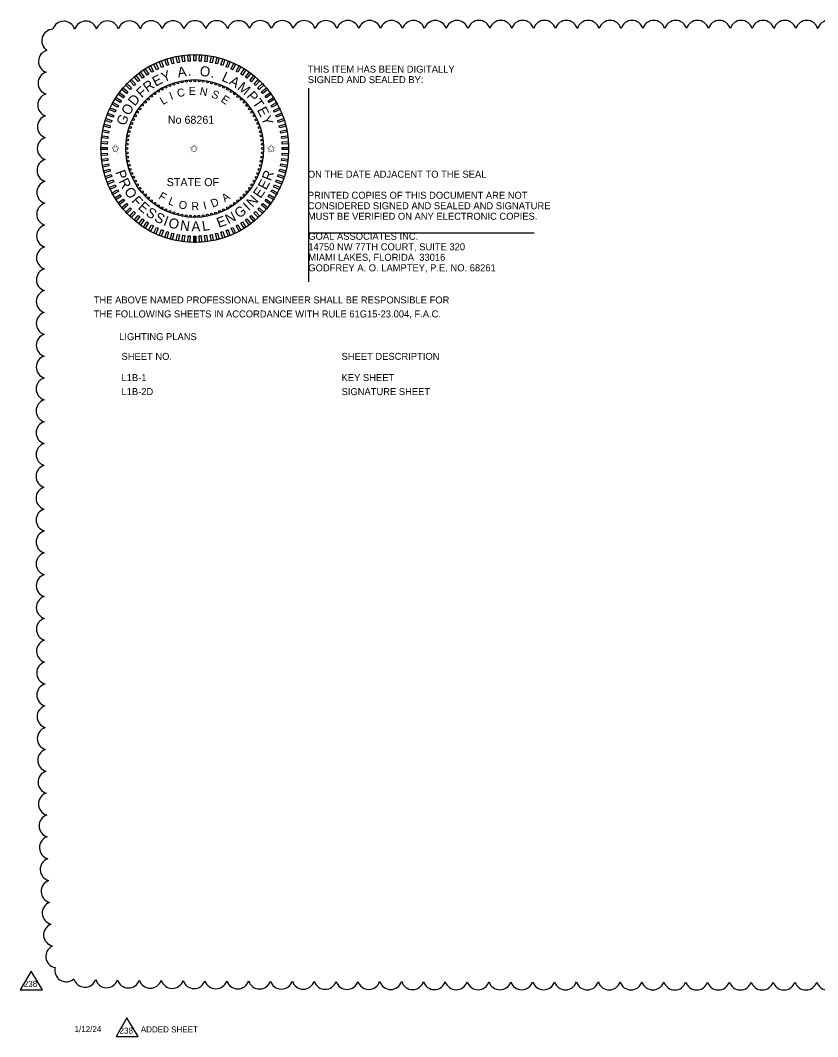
# Model space of a CAD drawing. Extents: x -811.2 to -767.6, y -2295.2 to -2235.1.
# Drawn here: x -811.23 to -803.27, y -2294.97 to -2284.82 of the extents above; entities that cross this region are included whole.
import ezdxf

# ---------------------------------------------------------------- set-up
doc = ezdxf.new("R2010")
doc.units = 0
for name, color, linetype in [('AdhocPoint_dp', 7, 'Continuous'), ('Cloud_dp', 7, 'Continuous'), ('PlotBorder_dp', 7, 'Continuous'), ('TextMinor', 7, 'Continuous'), ('TextMisc', 7, 'Continuous'), ('TextShtNo', 7, 'Continuous')]:
    doc.layers.add(name, color=color, linetype=linetype)

msp = doc.modelspace()

# ---------------------------------------------------------------- linework, layer by layer
at = {"layer": 'AdhocPoint_dp'}
for p, q in [((-808.355, -2285.496), (-808.355, -2287.431)), ((-808.355, -2286.941), (-806.098, -2286.941))]:
    msp.add_line(p, q, dxfattribs=at)
at = {"layer": 'Cloud_dp'}
for points in [[(-811.125, -2294.318), (-811.233, -2294.506), (-811.012, -2294.506)], [(-810.168, -2294.785), (-810.276, -2294.973), (-810.055, -2294.973)]]:
    msp.add_lwpolyline(points, close=True, dxfattribs=at)
for centre, start, end in [((-810.798, -2284.941), 18.0566, 163.0566), ((-810.58, -2284.94), 17.7998, 162.7998), ((-810.362, -2284.939), 17.7187, 162.7187), ((-810.143, -2284.938), 17.6743, 162.6743), ((-809.925, -2284.937), 17.6451, 162.6451), ((-809.707, -2284.937), 17.624, 162.624), ((-809.488, -2284.936), 17.6079, 162.6079), ((-809.27, -2284.936), 17.5951, 162.5951), ((-809.052, -2284.936), 17.5845, 162.5845), ((-808.834, -2284.935), 17.5756, 162.5756), ((-808.615, -2284.935), 17.568, 162.568), ((-808.397, -2284.935), 17.5614, 162.5614), ((-808.179, -2284.935), 17.5556, 162.5556), ((-807.96, -2284.934), 17.5505, 162.5505), ((-807.742, -2284.934), 17.5459, 162.5459), ((-807.524, -2284.934), 17.5417, 162.5417), ((-807.305, -2284.934), 17.5379, 162.5379), ((-807.087, -2284.934), 17.5344, 162.5344), ((-806.869, -2284.934), 17.5313, 162.5313), ((-806.65, -2284.933), 17.5283, 162.5283), ((-806.432, -2284.933), 17.5256, 162.5256), ((-806.214, -2284.933), 17.5231, 162.5231), ((-805.995, -2284.933), 17.5207, 162.5207), ((-805.777, -2284.933), 17.5185, 162.5185), ((-805.559, -2284.933), 17.5164, 162.5164), ((-805.34, -2284.933), 17.5145, 162.5145), ((-805.122, -2284.933), 17.5126, 162.5126), ((-804.904, -2284.933), 17.5109, 162.5109), ((-804.685, -2284.933), 17.5092, 162.5092), ((-804.467, -2284.933), 17.5077, 162.5077), ((-804.249, -2284.933), 17.5062, 162.5062), ((-804.03, -2284.933), 17.5048, 162.5048), ((-803.812, -2284.933), 17.5034, 162.5034), ((-803.594, -2284.933), 17.5021, 162.5021), ((-803.375, -2284.933), 17.5009, 162.5009), ((-803.157, -2284.933), 17.5, 162.5), ((-810.905, -2285.022), 91.4771, 236.4771), ((-810.937, -2285.228), 105.908, 250.908), ((-810.942, -2285.446), 106.4168, 251.4168), ((-810.945, -2285.664), 106.6762, 251.6762), ((-810.948, -2285.882), 106.841, 251.841), ((-810.95, -2286.1), 106.9576, 251.9576), ((-810.952, -2286.318), 107.0457, 252.0457), ((-810.954, -2286.537), 107.1154, 252.1154), ((-810.955, -2286.755), 107.1722, 252.1722), ((-810.956, -2286.973), 107.2198, 252.2198), ((-810.957, -2287.192), 107.2603, 252.2603), ((-810.958, -2287.41), 107.2954, 252.2954), ((-810.959, -2287.628), 107.3262, 252.3262), ((-810.96, -2287.847), 107.3535, 252.3535), ((-810.96, -2288.065), 107.3779, 252.3779), ((-810.96, -2288.283), 107.3998, 252.3998), ((-810.961, -2288.501), 107.4198, 252.4198), ((-810.961, -2288.72), 107.438, 252.438), ((-810.961, -2288.938), 107.4547, 252.4547), ((-810.961, -2289.156), 107.4701, 252.4701), ((-810.962, -2289.375), 107.4843, 252.4843), ((-810.962, -2289.593), 107.499, 252.499), ((-810.961, -2289.811), 107.5356, 252.5356), ((-810.961, -2290.03), 107.5822, 252.5822), ((-810.961, -2290.248), 107.6325, 252.6325), ((-810.96, -2290.466), 107.6869, 252.6869), ((-810.959, -2290.685), 107.7461, 252.7461), ((-810.958, -2290.903), 107.8108, 252.8108), ((-810.957, -2291.121), 107.8818, 252.8818), ((-810.955, -2291.339), 107.9604, 252.9604), ((-810.954, -2291.558), 108.0479, 253.0479), ((-810.951, -2291.776), 108.1461, 253.1461), ((-810.949, -2291.994), 108.2576, 253.2576), ((-810.945, -2292.212), 108.3854, 253.3854), ((-810.942, -2292.431), 108.534, 253.534), ((-810.938, -2292.649), 108.7099, 253.7099), ((-810.932, -2292.867), 108.9225, 253.9225), ((-810.927, -2293.085), 109.1867, 254.1867), ((-810.92, -2293.303), 109.5275, 254.5275), ((-810.911, -2293.521), 109.9909, 254.9909), ((-810.9, -2293.738), 110.6749, 255.6749), ((-810.886, -2293.956), 111.8417, 256.8417), ((-810.864, -2294.171), 114.6718, 259.6718), ((-810.774, -2294.311), 166.2299, 311.2299), ((-810.588, -2294.365), 196.1072, 341.1072), ((-810.37, -2294.37), 196.5738, 341.5738), ((-810.152, -2294.373), 196.7877, 341.7877), ((-809.934, -2294.375), 196.9179, 341.9179), ((-809.715, -2294.377), 197.008, 342.008), ((-809.497, -2294.379), 197.075, 342.075), ((-809.279, -2294.381), 197.1274, 342.1274), ((-809.061, -2294.382), 197.1699, 342.1699), ((-808.842, -2294.383), 197.2052, 342.2052), ((-808.624, -2294.384), 197.2352, 342.2352), ((-808.406, -2294.385), 197.261, 342.261), ((-808.187, -2294.386), 197.2836, 342.2836), ((-807.969, -2294.387), 197.3036, 342.3036), ((-807.751, -2294.387), 197.3214, 342.3214), ((-807.532, -2294.388), 197.3374, 342.3374), ((-807.314, -2294.389), 197.3519, 342.3519), ((-807.096, -2294.389), 197.3651, 342.3651), ((-806.878, -2294.39), 197.3773, 342.3773), ((-806.659, -2294.39), 197.3884, 342.3884), ((-806.441, -2294.391), 197.3987, 342.3987), ((-806.223, -2294.391), 197.4083, 342.4083), ((-806.004, -2294.391), 197.4172, 342.4172), ((-805.786, -2294.392), 197.4256, 342.4256), ((-805.568, -2294.392), 197.4334, 342.4334), ((-805.349, -2294.392), 197.4407, 342.4407), ((-805.131, -2294.392), 197.4476, 342.4476), ((-804.913, -2294.392), 197.4542, 342.4542), ((-804.694, -2294.393), 197.4604, 342.4604), ((-804.476, -2294.393), 197.4662, 342.4662), ((-804.258, -2294.393), 197.4718, 342.4718), ((-804.039, -2294.393), 197.4771, 342.4771), ((-803.821, -2294.393), 197.4821, 342.4821), ((-803.603, -2294.393), 197.487, 342.487), ((-803.384, -2294.393), 197.4916, 342.4916), ((-803.166, -2294.393), 197.496, 342.496)]:
    msp.add_arc(centre, 0.114, start, end, dxfattribs=at)
at = {"layer": 'TextMinor'}
for radius in [0.938, 0.688]:
    msp.add_circle((-809.49, -2286.099), radius, dxfattribs=at)
at = {"layer": 'TextShtNo'}
for p, q in [((-809.5, -2287.037), (-809.5, -2286.974)), ((-809.49, -2287.037), (-809.49, -2286.974)), ((-809.48, -2287.037), (-809.48, -2286.974))]:
    msp.add_line(p, q, dxfattribs=at)
for points in [[(-809.698, -2285.249), (-809.717, -2285.254), (-809.733, -2285.194), (-809.713, -2285.189)], [(-809.644, -2285.238), (-809.664, -2285.242), (-809.676, -2285.18), (-809.656, -2285.176)], [(-809.59, -2285.23), (-809.61, -2285.232), (-809.618, -2285.17), (-809.598, -2285.168)], [(-809.535, -2285.225), (-809.555, -2285.227), (-809.559, -2285.164), (-809.539, -2285.163)], [(-809.48, -2285.224), (-809.5, -2285.224), (-809.5, -2285.162), (-809.48, -2285.162)], [(-809.425, -2285.227), (-809.445, -2285.225), (-809.441, -2285.163), (-809.421, -2285.164)], [(-809.37, -2285.232), (-809.39, -2285.23), (-809.383, -2285.168), (-809.363, -2285.17)], [(-809.316, -2285.242), (-809.336, -2285.238), (-809.324, -2285.177), (-809.304, -2285.18)], [(-809.263, -2285.254), (-809.282, -2285.249), (-809.267, -2285.189), (-809.247, -2285.194)], [(-809.95, -2285.355), (-809.967, -2285.366), (-810.001, -2285.313), (-809.984, -2285.302)], [(-809.903, -2285.328), (-809.92, -2285.337), (-809.951, -2285.283), (-809.933, -2285.273)], [(-809.853, -2285.303), (-809.872, -2285.312), (-809.898, -2285.255), (-809.88, -2285.247)], [(-809.803, -2285.282), (-809.822, -2285.289), (-809.845, -2285.231), (-809.826, -2285.224)], [(-809.751, -2285.264), (-809.77, -2285.27), (-809.789, -2285.211), (-809.77, -2285.205)], [(-809.21, -2285.27), (-809.229, -2285.264), (-809.21, -2285.205), (-809.191, -2285.211)], [(-809.159, -2285.289), (-809.177, -2285.282), (-809.154, -2285.224), (-809.136, -2285.231)], [(-809.108, -2285.312), (-809.127, -2285.303), (-809.1, -2285.247), (-809.082, -2285.255)], [(-809.06, -2285.337), (-809.077, -2285.328), (-809.047, -2285.273), (-809.03, -2285.283)], [(-809.013, -2285.366), (-809.03, -2285.355), (-808.996, -2285.302), (-808.979, -2285.313)], [(-810.04, -2285.419), (-810.056, -2285.431), (-810.095, -2285.383), (-810.08, -2285.37)], [(-809.996, -2285.385), (-810.013, -2285.397), (-810.049, -2285.347), (-810.033, -2285.335)], [(-808.968, -2285.397), (-808.984, -2285.385), (-808.947, -2285.335), (-808.931, -2285.347)], [(-808.925, -2285.432), (-808.94, -2285.419), (-808.9, -2285.371), (-808.885, -2285.383)], [(-810.158, -2285.534), (-810.171, -2285.549), (-810.219, -2285.509), (-810.206, -2285.494)], [(-810.121, -2285.493), (-810.135, -2285.508), (-810.18, -2285.465), (-810.167, -2285.45)], [(-810.082, -2285.454), (-810.096, -2285.468), (-810.139, -2285.423), (-810.124, -2285.409)], [(-808.884, -2285.468), (-808.898, -2285.455), (-808.856, -2285.409), (-808.841, -2285.423)], [(-808.845, -2285.508), (-808.859, -2285.493), (-808.814, -2285.45), (-808.8, -2285.465)], [(-808.809, -2285.549), (-808.822, -2285.534), (-808.774, -2285.494), (-808.761, -2285.51)], [(-810.223, -2285.622), (-810.234, -2285.639), (-810.287, -2285.605), (-810.276, -2285.588)], [(-810.192, -2285.577), (-810.204, -2285.593), (-810.254, -2285.556), (-810.243, -2285.54)], [(-808.776, -2285.593), (-808.788, -2285.577), (-808.738, -2285.54), (-808.726, -2285.556)], [(-808.746, -2285.639), (-808.757, -2285.622), (-808.704, -2285.588), (-808.693, -2285.606)], [(-810.278, -2285.717), (-810.286, -2285.736), (-810.343, -2285.709), (-810.334, -2285.691)], [(-810.252, -2285.669), (-810.262, -2285.686), (-810.316, -2285.656), (-810.307, -2285.639)], [(-808.718, -2285.687), (-808.728, -2285.669), (-808.673, -2285.639), (-808.664, -2285.657)], [(-808.694, -2285.736), (-808.703, -2285.718), (-808.646, -2285.691), (-808.638, -2285.709)], [(-810.319, -2285.819), (-810.325, -2285.838), (-810.385, -2285.819), (-810.379, -2285.8)], [(-810.3, -2285.768), (-810.307, -2285.786), (-810.365, -2285.763), (-810.358, -2285.745)], [(-808.673, -2285.787), (-808.68, -2285.768), (-808.622, -2285.745), (-808.615, -2285.764)], [(-808.655, -2285.839), (-808.661, -2285.819), (-808.602, -2285.8), (-808.595, -2285.819)], [(-810.335, -2285.872), (-810.34, -2285.891), (-810.401, -2285.876), (-810.396, -2285.856)], [(-808.64, -2285.892), (-808.645, -2285.872), (-808.585, -2285.856), (-808.58, -2285.876)], [(-810.357, -2285.979), (-810.36, -2285.999), (-810.421, -2285.992), (-810.419, -2285.972)], [(-810.348, -2285.925), (-810.352, -2285.945), (-810.413, -2285.933), (-810.409, -2285.914)], [(-808.629, -2285.945), (-808.632, -2285.925), (-808.571, -2285.914), (-808.567, -2285.934)], [(-808.621, -2286), (-808.623, -2285.98), (-808.561, -2285.972), (-808.559, -2285.992)], [(-810.365, -2286.089), (-810.365, -2286.109), (-810.428, -2286.109), (-810.428, -2286.089)], [(-810.363, -2286.034), (-810.364, -2286.054), (-810.426, -2286.05), (-810.425, -2286.03)], [(-808.616, -2286.054), (-808.617, -2286.034), (-808.555, -2286.03), (-808.554, -2286.051)], [(-808.615, -2286.109), (-808.615, -2286.089), (-808.553, -2286.089), (-808.553, -2286.109)], [(-810.364, -2286.144), (-810.363, -2286.164), (-810.425, -2286.168), (-810.426, -2286.148)], [(-810.36, -2286.199), (-810.357, -2286.219), (-810.419, -2286.227), (-810.421, -2286.207)], [(-808.623, -2286.219), (-808.621, -2286.199), (-808.559, -2286.207), (-808.561, -2286.227)], [(-808.617, -2286.164), (-808.616, -2286.144), (-808.554, -2286.148), (-808.555, -2286.168)], [(-810.352, -2286.253), (-810.348, -2286.273), (-810.409, -2286.285), (-810.413, -2286.265)], [(-810.34, -2286.307), (-810.335, -2286.327), (-810.396, -2286.342), (-810.401, -2286.323)], [(-808.645, -2286.327), (-808.64, -2286.307), (-808.58, -2286.323), (-808.585, -2286.342)], [(-808.632, -2286.273), (-808.629, -2286.253), (-808.567, -2286.265), (-808.571, -2286.285)], [(-810.325, -2286.36), (-810.319, -2286.379), (-810.379, -2286.398), (-810.385, -2286.379)], [(-810.307, -2286.412), (-810.3, -2286.431), (-810.358, -2286.454), (-810.366, -2286.435)], [(-808.68, -2286.431), (-808.673, -2286.412), (-808.615, -2286.435), (-808.622, -2286.454)], [(-808.661, -2286.379), (-808.655, -2286.36), (-808.595, -2286.379), (-808.602, -2286.399)], [(-810.286, -2286.463), (-810.278, -2286.481), (-810.334, -2286.507), (-810.343, -2286.489)], [(-810.262, -2286.512), (-810.252, -2286.53), (-810.307, -2286.56), (-810.317, -2286.542)], [(-808.728, -2286.53), (-808.719, -2286.512), (-808.664, -2286.542), (-808.674, -2286.56)], [(-808.703, -2286.481), (-808.694, -2286.463), (-808.638, -2286.489), (-808.646, -2286.508)], [(-810.234, -2286.56), (-810.224, -2286.577), (-810.276, -2286.61), (-810.287, -2286.593)], [(-810.204, -2286.605), (-810.192, -2286.622), (-810.243, -2286.658), (-810.255, -2286.642)], [(-808.788, -2286.622), (-808.776, -2286.605), (-808.726, -2286.642), (-808.738, -2286.659)], [(-808.757, -2286.577), (-808.746, -2286.56), (-808.693, -2286.593), (-808.704, -2286.61)], [(-810.171, -2286.649), (-810.158, -2286.665), (-810.206, -2286.705), (-810.219, -2286.689)], [(-810.135, -2286.691), (-810.121, -2286.706), (-810.167, -2286.748), (-810.18, -2286.734)], [(-808.859, -2286.706), (-808.845, -2286.691), (-808.8, -2286.734), (-808.814, -2286.748)], [(-808.822, -2286.665), (-808.81, -2286.649), (-808.761, -2286.689), (-808.774, -2286.705)], [(-810.097, -2286.73), (-810.082, -2286.744), (-810.125, -2286.789), (-810.139, -2286.776)], [(-810.056, -2286.767), (-810.04, -2286.78), (-810.08, -2286.828), (-810.096, -2286.815)], [(-810.013, -2286.801), (-809.996, -2286.813), (-810.033, -2286.864), (-810.049, -2286.852)], [(-808.984, -2286.813), (-808.968, -2286.801), (-808.931, -2286.852), (-808.947, -2286.864)], [(-808.94, -2286.78), (-808.925, -2286.767), (-808.885, -2286.815), (-808.9, -2286.828)], [(-808.899, -2286.744), (-808.884, -2286.73), (-808.841, -2286.776), (-808.856, -2286.79)], [(-809.968, -2286.833), (-809.951, -2286.843), (-809.984, -2286.896), (-810.001, -2286.885)], [(-809.921, -2286.861), (-809.903, -2286.871), (-809.933, -2286.926), (-809.951, -2286.916)], [(-809.872, -2286.887), (-809.854, -2286.895), (-809.88, -2286.952), (-809.898, -2286.943)], [(-809.822, -2286.909), (-809.803, -2286.917), (-809.826, -2286.975), (-809.845, -2286.967)], [(-809.77, -2286.928), (-809.751, -2286.935), (-809.77, -2286.994), (-809.79, -2286.988)], [(-809.229, -2286.935), (-809.21, -2286.928), (-809.191, -2286.988), (-809.21, -2286.994)], [(-809.177, -2286.917), (-809.159, -2286.909), (-809.136, -2286.967), (-809.154, -2286.975)], [(-809.127, -2286.895), (-809.109, -2286.887), (-809.082, -2286.943), (-809.1, -2286.952)], [(-809.077, -2286.871), (-809.06, -2286.861), (-809.03, -2286.916), (-809.047, -2286.926)], [(-809.03, -2286.844), (-809.013, -2286.833), (-808.979, -2286.885), (-808.996, -2286.896)], [(-809.718, -2286.944), (-809.698, -2286.949), (-809.714, -2287.01), (-809.733, -2287.005)], [(-809.664, -2286.957), (-809.644, -2286.961), (-809.656, -2287.022), (-809.676, -2287.018)], [(-809.61, -2286.966), (-809.59, -2286.969), (-809.598, -2287.031), (-809.618, -2287.028)], [(-809.555, -2286.972), (-809.535, -2286.973), (-809.539, -2287.035), (-809.559, -2287.034)], [(-809.5, -2286.974), (-809.48, -2286.974), (-809.48, -2287.037), (-809.5, -2287.037)], [(-809.445, -2286.973), (-809.425, -2286.972), (-809.421, -2287.034), (-809.441, -2287.036)], [(-809.391, -2286.969), (-809.371, -2286.966), (-809.363, -2287.028), (-809.383, -2287.031)], [(-809.336, -2286.961), (-809.316, -2286.957), (-809.305, -2287.018), (-809.324, -2287.022)], [(-809.282, -2286.949), (-809.263, -2286.944), (-809.247, -2287.005), (-809.267, -2287.01)]]:
    msp.add_lwpolyline(points, close=True, dxfattribs=at)
for centre in [(-809.816, -2285.505), (-809.778, -2285.486), (-809.739, -2285.469), (-809.699, -2285.455), (-809.658, -2285.443), (-809.617, -2285.434), (-809.574, -2285.427), (-809.532, -2285.423), (-809.49, -2285.422), (-809.447, -2285.423), (-809.405, -2285.427), (-809.363, -2285.434), (-809.321, -2285.443), (-809.28, -2285.455), (-809.24, -2285.47), (-809.201, -2285.486), (-809.163, -2285.506), (-809.953, -2285.605), (-809.922, -2285.577), (-809.888, -2285.551), (-809.853, -2285.527), (-809.127, -2285.528), (-809.091, -2285.551), (-809.058, -2285.578), (-809.026, -2285.606), (-810.038, -2285.701), (-810.012, -2285.667), (-809.984, -2285.635), (-808.996, -2285.636), (-808.968, -2285.668), (-808.942, -2285.701), (-810.103, -2285.81), (-810.084, -2285.772), (-810.062, -2285.736), (-808.918, -2285.737), (-808.896, -2285.773), (-808.877, -2285.811), (-810.134, -2285.889), (-810.12, -2285.849), (-808.86, -2285.85), (-808.846, -2285.89), (-810.162, -2286.014), (-810.155, -2285.972), (-810.146, -2285.93), (-808.834, -2285.931), (-808.825, -2285.973), (-808.818, -2286.015), (-810.168, -2286.099), (-810.166, -2286.056), (-808.814, -2286.057), (-808.813, -2286.1), (-810.166, -2286.141), (-810.162, -2286.184), (-810.156, -2286.226), (-808.825, -2286.227), (-808.818, -2286.185), (-808.814, -2286.142), (-810.146, -2286.267), (-810.135, -2286.308), (-808.846, -2286.309), (-808.834, -2286.268), (-810.12, -2286.348), (-810.103, -2286.387), (-810.084, -2286.425), (-808.897, -2286.426), (-808.877, -2286.388), (-808.86, -2286.349), (-810.062, -2286.462), (-810.039, -2286.497), (-810.012, -2286.531), (-808.968, -2286.532), (-808.942, -2286.498), (-808.918, -2286.463), (-809.984, -2286.563), (-809.954, -2286.593), (-809.922, -2286.621), (-809.059, -2286.622), (-809.027, -2286.593), (-808.997, -2286.563), (-809.889, -2286.647), (-809.854, -2286.671), (-809.817, -2286.693), (-809.779, -2286.712), (-809.74, -2286.729), (-809.241, -2286.729), (-809.202, -2286.712), (-809.164, -2286.693), (-809.128, -2286.672), (-809.092, -2286.648), (-809.7, -2286.743), (-809.659, -2286.755), (-809.618, -2286.765), (-809.576, -2286.771), (-809.533, -2286.775), (-809.49, -2286.777), (-809.448, -2286.775), (-809.406, -2286.771), (-809.364, -2286.765), (-809.322, -2286.756), (-809.281, -2286.744)]:
    msp.add_circle(centre, 0.01, dxfattribs=at)

# ---------------------------------------------------------------- texts
at = {"layer": 'Cloud_dp'}
for p in [(-811.198, -2294.476), (-810.241, -2294.943)]:
    msp.add_text('238', height=0.06, rotation=0, dxfattribs=at).set_placement(p)
at = {"layer": 'PlotBorder_dp'}
for s, p in [('THIS ITEM HAS BEEN DIGITALLY', (-808.36, -2285.341)), ('SIGNED AND SEALED BY:', (-808.36, -2285.446)), ('ON THE DATE ADJACENT TO THE SEAL', (-808.36, -2286.391)), ('PRINTED COPIES OF THIS DOCUMENT ARE NOT ', (-808.36, -2286.601)), ('CONSIDERED SIGNED AND SEALED AND SIGNATURE ', (-808.36, -2286.706)), ('MUST BE VERIFIED ON ANY ELECTRONIC COPIES.', (-808.36, -2286.811)), ('GOAL ASSOCIATES INC.', (-808.355, -2287.011)), ('14750 NW 77TH COURT, SUITE 320', (-808.355, -2287.116)), ('MIAMI LAKES, FLORIDA  33016', (-808.355, -2287.221)), ('GODFREY A. O. LAMPTEY, P.E. NO. 68261', (-808.355, -2287.326)), ('THE ABOVE NAMED PROFESSIONAL ENGINEER SHALL BE RESPONSIBLE FOR ', (-810.499, -2287.647)), ('THE FOLLOWING SHEETS IN ACCORDANCE WITH RULE 61G15-23.004, F.A.C.', (-810.499, -2287.787)), ('LIGHTING PLANS', (-810.245, -2288.014))]:
    msp.add_text(s, height=0.07, dxfattribs=at).set_placement(p)
at = {"layer": 'TextMinor'}
for s, p in [('1/12/24', (-810.691, -2294.928)), ('ADDED SHEET', (-810.029, -2294.931))]:
    msp.add_text(s, height=0.06, dxfattribs=at).set_placement(p)
at = {"layer": 'TextMisc'}
for s, p in [('SHEET NO.', (-810.222, -2288.211)), ('SHEET DESCRIPTION', (-808.023, -2288.211)), ('L1B-1', (-810.222, -2288.423)), ('KEY SHEET', (-808.023, -2288.423)), ('L1B-2D', (-810.222, -2288.563)), ('SIGNATURE SHEET', (-808.023, -2288.563))]:
    msp.add_text(s, height=0.07, dxfattribs=at).set_placement(p)
at = {"layer": 'TextShtNo'}
for s, height, rotation, p in [('A', 0.1, 8.8088, (-809.655, -2285.389)), ('O', 0.1, 352.1877, (-809.445, -2285.371)), ('E', 0.1, 28.1055, (-809.881, -2285.483)), ('Y', 0.1, 21.0633, (-809.802, -2285.44)), ('.', 0.1, 1.0418, (-809.558, -2285.373)), ('.', 0.1, 343.5268, (-809.336, -2285.386)), ('L', 0.1, 334.6727, (-809.228, -2285.418)), ('A', 0.1, 328.4096, (-809.155, -2285.451)), ('F', 0.1, 42.3772, (-810.02, -2285.598)), ('R', 0.1, 35.9269, (-809.961, -2285.542)), ('C', 0.08, 12.2025, (-809.658, -2285.588)), ('E', 0.08, 0.4186, (-809.55, -2285.564)), ('N', 0.08, 349.2914, (-809.445, -2285.563)), ('M', 0.1, 320.6426, (-809.071, -2285.502)), ('D', 0.1, 50.8569, (-810.089, -2285.682)), ('L', 0.08, 30.4021, (-809.809, -2285.666)), ('I', 0.08, 20.0117, (-809.726, -2285.615)), ('S', 0.08, 337.0221, (-809.332, -2285.584)), ('E', 0.08, 325.8663, (-809.236, -2285.625)), ('P', 0.1, 311.1966, (-808.978, -2285.579)), ('T', 0.1, 304.4563, (-808.921, -2285.643)), ('O', 0.1, 59.5178, (-810.145, -2285.777)), ('E', 0.1, 297.6315, (-808.871, -2285.714)), ('G', 0.1, 68.0518, (-810.185, -2285.878)), ('Y', 0.1, 290.5893, (-808.828, -2285.793)), ('P', 0.1, 289.4055, (-810.285, -2286.334)), ('R', 0.1, 69.5134, (-808.73, -2286.429)), ('R', 0.1, 296.1458, (-810.252, -2286.425)), ('E', 0.1, 62.4712, (-808.776, -2286.52)), ('O', 0.1, 303.9671, (-810.2, -2286.526)), ('E', 0.1, 55.4289, (-808.833, -2286.604)), ('F', 0.1, 312.628, (-810.128, -2286.628)), ('F', 0.08, 328.7241, (-809.858, -2286.596)), ('L', 0.08, 339.2916, (-809.761, -2286.655)), ('O', 0.08, 349.6821, (-809.656, -2286.695)), ('D', 0.08, 22.0128, (-809.312, -2286.691)), ('A', 0.08, 34.4992, (-809.188, -2286.639)), ('N', 0.1, 47.1788, (-808.912, -2286.693)), ('E', 0.1, 319.0783, (-810.064, -2286.696)), ('S', 0.1, 326.1206, (-809.987, -2286.762)), ('R', 0.08, 2.3398, (-809.522, -2286.717)), ('I', 0.08, 14.2037, (-809.394, -2286.71)), ('G', 0.1, 35.1115, (-809.049, -2286.801)), ('I', 0.1, 43.6456, (-808.95, -2286.728)), ('S', 0.1, 333.193, (-809.902, -2286.819)), ('I', 0.1, 340.2654, (-809.81, -2286.864)), ('O', 0.1, 343.7986, (-809.762, -2286.882)), ('N', 0.1, 352.4595, (-809.641, -2286.914)), ('A', 0.1, 0.7097, (-809.523, -2286.927)), ('L', 0.1, 8.4767, (-809.41, -2286.924)), ('E', 0.1, 19.8191, (-809.25, -2286.892)), ('N', 0.1, 26.8614, (-809.154, -2286.857))]:
    msp.add_text(s, height=height, rotation=rotation, dxfattribs=at).set_placement(p)
for s, p in [('No 68261', (-809.759, -2285.852)), ('✩', (-810.325, -2286.137)), ('✩', (-809.54, -2286.137)), ('✩', (-808.769, -2286.137)), ('STATE OF', (-809.77, -2286.475))]:
    msp.add_text(s, height=0.08, dxfattribs=at).set_placement(p)

doc.saveas('drawing.dxf')
